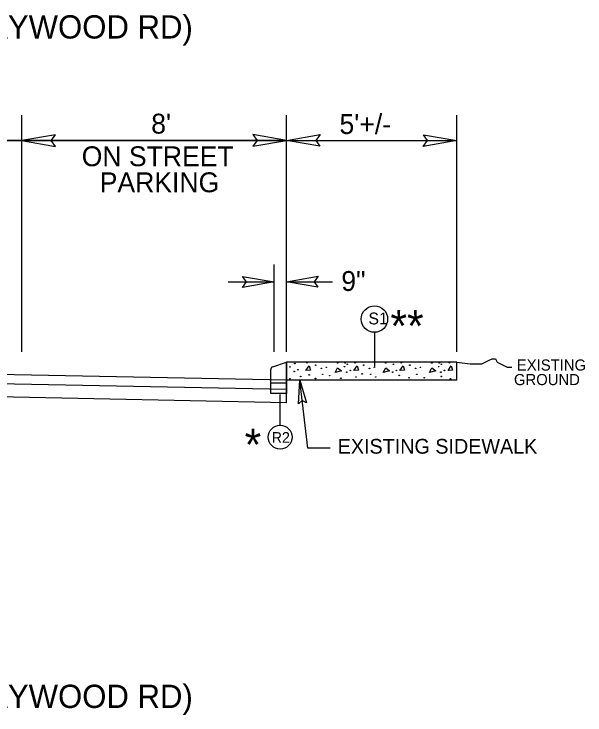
# Model space of a CAD drawing. Extents: x 1022283 to 1026986, y 174822 to 180471.
# Drawn here: x 1024119 to 1024579, y 176179 to 176744 of the extents above; entities that cross this region are included whole.
import ezdxf

# ---------------------------------------------------------------- set-up
doc = ezdxf.new("R2010")
doc.units = 0
for name, color, linetype in [('Default', 7, 'Continuous'), ('Prop Dimension', 7, 'Continuous'), ('Prop Terminator CELL', 7, 'Continuous'), ('Typical Curb CELL', 7, 'Continuous'), ('Typical ID Circle CELL', 7, 'Continuous'), ('Typical Slope Point Local CELL', 7, 'Continuous'), ('Typical Text General CELL', 7, 'Continuous'), ('Typical Text ID Circle CELL', 7, 'Continuous')]:
    doc.layers.add(name, color=color, linetype=linetype)

# ---------------------------------------------------------------- blocks, each defined once
blk = doc.blocks.new('Terminator')
at = {"layer": 'Prop Terminator CELL'}
blk.add_lwpolyline([(-9, 1.55), (0, 0), (-9.05, -1.6), (-7.9, 0)], close=True, dxfattribs=at)

msp = doc.modelspace()

# ---------------------------------------------------------------- linework, layer by layer
at = {"layer": 'Default'}
for p, q in [((1024125.06, 176471.53), (1024125.06, 176662.34)), ((1024338.25, 176471.53), (1024338.25, 176662.34)), ((1024475.62, 176471.53), (1024475.62, 176662.34)), ((1023830.54, 176641.78), (1024338.25, 176641.78)), ((1024338.25, 176641.78), (1023830.54, 176641.78)), ((1024338.25, 176641.78), (1024475.62, 176641.78)), ((1024328.25, 176471.53), (1024328.25, 176542.03)), ((1024291.21, 176528.01), (1024328.25, 176528.01)), ((1024338.25, 176528.01), (1024375.29, 176528.01))]:
    msp.add_line(p, q, dxfattribs=at)
at = {"layer": 'Prop Dimension'}
for p, q in [((1024338.25, 176448.73), (1023830.54, 176458.89)), ((1024338.25, 176448.73), (1023830.54, 176458.89)), ((1024338.25, 176441.23), (1023830.54, 176451.38)), ((1024338.25, 176441.23), (1023830.54, 176451.38)), ((1024355.36, 176394), (1024349.04, 176448.73)), ((1024338.25, 176430.65), (1023830.54, 176440.8)), ((1024373.51, 176394), (1024355.36, 176394))]:
    msp.add_line(p, q, dxfattribs=at)
at = {"layer": 'Prop Terminator CELL'}
for points in [[(1024152.06, 176646.43), (1024125.06, 176641.78), (1024152.21, 176636.98), (1024148.76, 176641.78)], [(1024311.25, 176637.13), (1024338.25, 176641.78), (1024311.1, 176646.58), (1024314.55, 176641.78)], [(1024365.25, 176637.13), (1024338.25, 176641.78), (1024365.4, 176646.58), (1024361.95, 176641.78)], [(1024448.62, 176646.43), (1024475.62, 176641.78), (1024448.47, 176636.98), (1024451.92, 176641.78)], [(1024302.94, 176532.37), (1024328.25, 176528.01), (1024302.8, 176523.51), (1024306.03, 176528.01)], [(1024363.56, 176523.65), (1024338.25, 176528.01), (1024363.7, 176532.51), (1024360.47, 176528.01)]]:
    msp.add_lwpolyline(points, close=True, dxfattribs=at)
at = {"layer": 'Typical Curb CELL'}
for p, q in [((1024327.28, 176459.6), (1024338.25, 176463.26)), ((1024338.25, 176432.25), (1024338.25, 176463.26)), ((1024338.25, 176452.92), (1024338.25, 176463.26)), ((1024338.25, 176452.92), (1024338.25, 176463.26)), ((1024475.62, 176463.26), (1024338.25, 176463.26)), ((1024338.25, 176430.65), (1024338.25, 176463.26)), ((1024338.25, 176432.25), (1024338.25, 176463.26)), ((1024338.25, 176452.92), (1024338.25, 176463.26)), ((1024338.25, 176452.92), (1024338.25, 176463.26)), ((1024475.62, 176463.26), (1024338.25, 176463.26)), ((1024338.25, 176430.65), (1024338.25, 176463.26)), ((1024338.25, 176463.26), (1024338.25, 176446.39)), ((1024353.82, 176456.63), (1024356.5, 176460.34)), ((1024353.82, 176456.63), (1024356.5, 176460.34)), ((1024356.5, 176460.34), (1024357.57, 176456.82)), ((1024356.5, 176460.34), (1024357.57, 176456.82)), ((1024392.58, 176456.63), (1024395.23, 176460.34)), ((1024392.58, 176456.63), (1024395.23, 176460.34)), ((1024395.23, 176460.34), (1024396.3, 176456.82)), ((1024395.23, 176460.34), (1024396.3, 176456.82)), ((1024429.71, 176456.63), (1024432.4, 176460.34)), ((1024429.71, 176456.63), (1024432.4, 176460.34)), ((1024432.4, 176460.34), (1024433.46, 176456.82)), ((1024432.4, 176460.34), (1024433.46, 176456.82)), ((1024468.47, 176456.63), (1024471.12, 176460.34)), ((1024468.47, 176456.63), (1024471.12, 176460.34)), ((1024471.12, 176460.34), (1024472.19, 176456.82)), ((1024471.12, 176460.34), (1024472.19, 176456.82)), ((1024475.62, 176448.73), (1024475.62, 176463.26)), ((1024475.62, 176448.73), (1024475.62, 176463.26)), ((1024325.6, 176446.39), (1024325.6, 176457.27)), ((1024357.57, 176456.82), (1024353.82, 176456.63)), ((1024357.57, 176456.82), (1024353.82, 176456.63)), ((1024377.56, 176455.04), (1024379.5, 176458.6)), ((1024377.56, 176455.04), (1024379.5, 176458.6)), ((1024382.7, 176456.27), (1024377.56, 176455.04)), ((1024382.7, 176456.27), (1024377.56, 176455.04)), ((1024379.5, 176458.6), (1024382.7, 176456.27)), ((1024379.5, 176458.6), (1024382.7, 176456.27)), ((1024396.3, 176456.82), (1024392.58, 176456.63)), ((1024396.3, 176456.82), (1024392.58, 176456.63)), ((1024416.29, 176455.04), (1024418.23, 176458.6)), ((1024416.29, 176455.04), (1024418.23, 176458.6)), ((1024421.42, 176456.27), (1024416.29, 176455.04)), ((1024421.42, 176456.27), (1024416.29, 176455.04)), ((1024418.23, 176458.6), (1024421.42, 176456.27)), ((1024418.23, 176458.6), (1024421.42, 176456.27)), ((1024433.46, 176456.82), (1024429.71, 176456.63)), ((1024433.46, 176456.82), (1024429.71, 176456.63)), ((1024453.45, 176455.04), (1024455.39, 176458.6)), ((1024453.45, 176455.04), (1024455.39, 176458.6)), ((1024458.59, 176456.27), (1024453.45, 176455.04)), ((1024458.59, 176456.27), (1024453.45, 176455.04)), ((1024455.39, 176458.6), (1024458.59, 176456.27)), ((1024455.39, 176458.6), (1024458.59, 176456.27)), ((1024472.19, 176456.82), (1024468.47, 176456.63)), ((1024472.19, 176456.82), (1024468.47, 176456.63)), ((1024475.62, 176448.73), (1024338.25, 176448.73)), ((1024338.25, 176446.39), (1024325.6, 176446.39)), ((1024325.6, 176437.95), (1024325.6, 176446.39)), ((1024338.25, 176446.39), (1024338.25, 176437.95)), ((1024338.25, 176437.95), (1024325.6, 176437.95))]:
    msp.add_line(p, q, dxfattribs=at)
for centre in [(1024345.05, 176462.14), (1024345.05, 176462.14), (1024354.9, 176462.83), (1024354.9, 176462.83), (1024361.81, 176460.89), (1024361.81, 176460.89), (1024379.51, 176462.66), (1024379.51, 176462.66), (1024385, 176459.65), (1024385, 176459.65), (1024385.53, 176462.66), (1024385.53, 176462.66), (1024387.26, 176461.6), (1024387.26, 176461.6), (1024393.64, 176462.83), (1024393.64, 176462.83), (1024400.54, 176460.89), (1024400.54, 176460.89), (1024418.24, 176462.66), (1024418.24, 176462.66), (1024424.42, 176461.6), (1024424.42, 176461.6), (1024430.79, 176462.83), (1024430.79, 176462.83), (1024437.7, 176460.89), (1024437.7, 176460.89), (1024455.4, 176462.66), (1024455.4, 176462.66), (1024460.89, 176459.65), (1024460.89, 176459.65), (1024461.42, 176462.66), (1024461.42, 176462.66), (1024463.15, 176461.6), (1024463.15, 176461.6), (1024469.53, 176462.83), (1024469.53, 176462.83), (1024341.11, 176459.45), (1024341.11, 176459.45), (1024344.55, 176455.76), (1024344.55, 176455.76), (1024347.53, 176457.18), (1024347.53, 176457.18), (1024366.41, 176458.23), (1024366.41, 176458.23), (1024370.31, 176459.12), (1024370.31, 176459.12), (1024386.77, 176455.22), (1024386.77, 176455.22), (1024389.75, 176456.64), (1024389.75, 176456.64), (1024405.15, 176458.23), (1024405.15, 176458.23), (1024409.04, 176459.12), (1024409.04, 176459.12), (1024423.92, 176455.22), (1024423.92, 176455.22), (1024426.9, 176456.64), (1024426.9, 176456.64), (1024442.3, 176458.23), (1024442.3, 176458.23), (1024446.2, 176459.12), (1024446.2, 176459.12), (1024462.66, 176455.22), (1024462.66, 176455.22), (1024465.64, 176456.64), (1024465.64, 176456.64), (1024341.11, 176449.95), (1024341.11, 176449.95), (1024349.7, 176451.7), (1024349.7, 176451.7), (1024356.55, 176452.99), (1024356.55, 176452.99), (1024361.65, 176450.08), (1024361.65, 176450.08), (1024367.47, 176453.46), (1024367.47, 176453.46), (1024373.08, 176452.41), (1024373.08, 176452.41), (1024382.06, 176450.34), (1024382.06, 176450.34), (1024394.27, 176451.31), (1024394.27, 176451.31), (1024399.24, 176453.83), (1024399.24, 176453.83), (1024406.2, 176453.46), (1024406.2, 176453.46), (1024410.22, 176451.31), (1024410.22, 176451.31), (1024429.15, 176452.6), (1024429.15, 176452.6), (1024437.03, 176450.73), (1024437.03, 176450.73), (1024443.36, 176453.46), (1024443.36, 176453.46), (1024449.3, 176450.73), (1024449.3, 176450.73), (1024463, 176451.7), (1024463, 176451.7), (1024470.43, 176449.76), (1024470.43, 176449.76)]:
    msp.add_circle(centre, 0.249, dxfattribs=at)
msp.add_arc((1024328.06, 176457.27), 2.46, 108.435, 180, dxfattribs=at)
at = {"layer": 'Typical ID Circle CELL'}
for p, q in [((1024409.15, 176487.35), (1024409.15, 176459.83)), ((1024333.17, 176412.47), (1024333.17, 176437.25))]:
    msp.add_line(p, q, dxfattribs=at)
for centre, radius in [((1024409.15, 176498), 10.65), ((1024333.17, 176402.89), 9.59)]:
    msp.add_circle(centre, radius, dxfattribs=at)
at = {"layer": 'Typical Slope Point Local CELL'}
msp.add_lwpolyline([(1024475.62, 176463.26), (1024486.4, 176461.92), (1024489.09, 176461.92), (1024493.13, 176461.92), (1024495.83, 176461.92), (1024498.52, 176463.26), (1024501.21, 176464.61), (1024503.91, 176465.96), (1024506.6, 176465.96), (1024507.95, 176463.26), (1024510.64, 176461.92), (1024513.34, 176460.57), (1024516.03, 176459.22), (1024518.72, 176459.22), (1024519.78, 176459.22)], dxfattribs=at)
msp.add_lwpolyline([(1024475.62, 176463.26), (1024486.4, 176461.92), (1024489.09, 176461.92), (1024493.13, 176461.92), (1024495.83, 176461.92), (1024498.52, 176463.26), (1024501.21, 176464.61), (1024503.91, 176465.96), (1024506.6, 176465.96), (1024507.95, 176463.26), (1024510.64, 176461.92), (1024513.34, 176460.57), (1024516.03, 176459.22), (1024518.72, 176459.22), (1024519.78, 176459.22)], dxfattribs=at)

# ---------------------------------------------------------------- block references
at = {"layer": 'Prop Dimension', "xscale": 2.0767499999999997, "yscale": 2.076749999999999, "rotation": 96.5883266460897}
msp.add_blockref('Terminator', (1024349.04, 176448.73), dxfattribs=at)

# ---------------------------------------------------------------- texts
at = {"layer": 'Prop Dimension'}
for s, height, p in [('-EL- US 19/23 BUS (HAYWOOD RD) ', 18.75, (1023846.26, 176723.95)), ("8'", 16, (1024229.28, 176647.38)), ("5'+/-", 16, (1024381, 176647.05)), ('ON STREET', 16, (1024173.27, 176621.12)), ('PARKING', 16, (1024187.8, 176600.14)), ('9"', 16, (1024382.48, 176520.65)), ('-EL- US 19/23 BUS (HAYWOOD RD) ', 18.75, (1023846.26, 176184.74))]:
    msp.add_text(s, height=height, dxfattribs=at).set_placement(p)
at = {"layer": 'Typical Slope Point Local CELL'}
for s, height, p in [('**', 25.771, (1024422.03, 176479.62)), ('EXISTING ', 8.938, (1024523.95, 176456.5)), ('EXISTING ', 8.938, (1024523.95, 176456.5)), ('GROUND', 8.938, (1024521.62, 176444.78)), ('GROUND', 8.938, (1024521.62, 176444.78)), ('*', 25.77, (1024304.56, 176383.96))]:
    msp.add_text(s, height=height, dxfattribs=at).set_placement(p)
at = {"layer": 'Typical Text General CELL'}
msp.add_text('EXISTING SIDEWALK', height=11.8979, dxfattribs=at).set_placement((1024379.55, 176389.57))
at = {"layer": 'Typical Text ID Circle CELL'}
for s, height, p in [('S1', 9.534, (1024404.35, 176493.7)), ('R2', 8.581, (1024326.37, 176398.34))]:
    msp.add_text(s, height=height, dxfattribs=at).set_placement(p)

doc.saveas('drawing.dxf')
